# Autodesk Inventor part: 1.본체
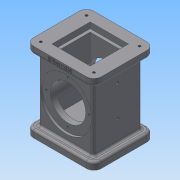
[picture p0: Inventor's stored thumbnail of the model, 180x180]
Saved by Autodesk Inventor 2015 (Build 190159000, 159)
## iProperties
Created: 2017-08
Part Number: 1.본체
Material: 일반
Document SubType Name: Modeling
Designer: owner
Density: 1 g/cm^3
Appearance: 기본값
Author: owner
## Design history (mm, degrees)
sketch "스케치1"
  geometry: L1 (-41, -46)-(41, -46); L2 (41, -46)-(41, 46); L3 (41, 46)-(-41, 46); L4 (-41, 46)-(-41, -46); L5 (-41, -46)-(41, 46); L6 (41, -46)-(-41, 46); 1 further point
  constraints: 12 end point, 2 midpoint, 2 parallel, 1 horizontal, 1 perpendicular
  dimensions: "d0" = 92 distance between parallel lines of L1 L3; "d1" = 82 distance between parallel lines of L4 L2
extrude "돌출1" new body sketch "스케치1" distance "d2" = 10; taper "d3" = 0 deg
sketch "스케치2"
  geometry: L1 (33, 37)-(-33, 37); L2 (-33, 37)-(-33, -37); L3 (-33, -37)-(33, -37); L4 (33, -37)-(33, 37); L5 (33, 37)-(-33, -37); L6 (-33, 37)-(33, -37); 1 further point
  constraints: 12 end point, 2 midpoint, 2 parallel, 1 horizontal, 1 perpendicular
  dimensions: "d4" = 74 distance between parallel lines of L1 L3; "d5" = 66 distance between parallel lines of L4 L2
extrude "돌출2" join sketch "스케치2" distance "d6" = 88; taper "d7" = 0 deg
sketch "스케치3"
  geometry: L1 (41, 46)-(-41, 46) reference; L2 (-41, 46)-(-41, -46) reference; L3 (-41, -46)-(41, -46) reference; L4 (41, -46)-(41, 46) reference; 1 further point
extrude "돌출3" join sketch "스케치3" distance "d8" = 10; taper "d9" = 0 deg
sketch "스케치5"
  geometry: L1 (26, -26)-(-26, -26); L2 (-26, -26)-(-26, 26); L3 (-26, 26)-(26, 26); L4 (26, 26)-(26, -26); L5 (26, -26)-(-26, 26); L6 (-26, -26)-(26, 26); 1 further point
  constraints: 12 end point, 2 midpoint, 2 parallel, 1 horizontal, 1 perpendicular
  dimensions: "d14" = 52 distance between parallel lines of L4 L2; "d15" = 52 distance between parallel lines of L1 L3 (= d14)
extrude "돌출5" cut sketch "스케치5" distance "d16" = 8; taper "d17" = 0 deg
sketch "스케치6"
  geometry: L1 (24, -24)-(-24, -24); L2 (-24, -24)-(-24, 24); L3 (-24, 24)-(24, 24); L4 (24, 24)-(24, -24); L5 (24, -24)-(-24, 24); L6 (-24, -24)-(24, 24); 1 further point
  constraints: 12 end point, 2 midpoint, 2 parallel, 1 horizontal, 1 perpendicular
  dimensions: "d18" = 48 distance between parallel lines of L4 L2; "d19" = 48 distance between parallel lines of L1 L3 (= d18)
extrude "돌출6" cut sketch "스케치6" distance "d20" = 16; taper "d21" = 0 deg
sketch "스케치7"
  geometry: L1 (-33, 10)-(-33, 98) reference; L2 (33, 10)-(33, 98) reference; L3 (-33, 54)-(33, 54); L4 (24, 0)-(-24, 0) reference; L5 (-33, 89)-(-30, 89); L6 (-30, 89)-(-30, 54); 1 further point
  constraints: 6 end point, 2 midpoint, 2 perpendicular, 2 point on line, 1 horizontal
  dimensions: "d22" = 54 distance between parallel lines of L4 L3; "d23" = 3 distance between parallel lines of L6 L1; "d24" = 70 diameter of L5.start L3
revolve "회전1" sketch "스케치7" stored, may be unused: angle "d25" = 90 deg
sketch "스케치8"
  geometry: C1 r 35 at (0, 0) reference; C2 r 24 at (0, 0); 1 further point
  constraints: 1 centre point, 1 coincident
  dimensions: "d26" = 48 diameter of C2
extrude "돌출7" cut sketch "스케치8" stored distance "d27" = 16; taper "d28" = 0 deg
sketch "스케치9" dims "d30" = 58
  geometry: L1 (0, 0)-(0, 29); 3 further points
  constraints: 2 coincident, 2 end point, 1 vertical, 1 vertical alignment, 2 other
hole "구멍1" sketch "스케치9" at (0, 29) diameter "d31" = 3.242; stored, may be unused: countersink angle "d35" = 90 deg, drill point angle "d37" = 118 deg; dims "d32" = 4, "d33" = 4, "d34" = 2, "d36" = 6
sketch "스케치10"
  geometry: L1 (31, -36)-(-31, -36); L2 (-31, -36)-(-31, 36); L3 (-31, 36)-(31, 36); L4 (31, 36)-(31, -36); L5 (31, -36)-(-31, 36); L6 (-31, -36)-(31, 36); 5 further points
  constraints: 12 end point, 4 coincident, 2 midpoint, 2 parallel, 1 horizontal, 1 perpendicular
  dimensions: "d41" = 62 distance between parallel lines of L4 L2; "d42" = 72 distance between parallel lines of L1 L3
hole "구멍2" sketch "스케치10" at (-31, 36), (31, 36), (31, -36), (-31, -36) diameter "d43" = 3.242; stored, may be unused: countersink angle "d47" = 90 deg, drill point angle "d49" = 118 deg; dims "d44" = 4, "d45" = 4, "d46" = 2, "d48" = 6
sketch "스케치12"
  geometry: L1 (22, -22)-(-22, -22); L2 (-22, -22)-(-22, 22); L3 (-22, 22)-(22, 22); L4 (22, 22)-(22, -22); L5 (22, -22)-(-22, 22); L6 (-22, -22)-(22, 22); 1 further point
  constraints: 12 end point, 2 midpoint, 2 parallel, 1 horizontal, 1 perpendicular
  dimensions: "d50" = 44 distance between parallel lines of L4 L2; "d51" = 44 distance between parallel lines of L1 L3
extrude "돌출8" cut sketch "스케치12" distance "d52" = 74; taper "d53" = 0 deg
fillet "모깎기1" dims "d54" = 3, "d55" = 10
sketch "스케치13"
  geometry: L1 (31, 36)-(-31, 36); L2 (-31, 36)-(-31, -36); L3 (-31, -36)-(31, -36); L4 (31, -36)-(31, 36); L5 (31, 36)-(-31, -36); L6 (-31, 36)-(31, -36); 5 further points
  constraints: 12 end point, 4 coincident, 2 midpoint, 2 parallel, 1 horizontal, 1 perpendicular
  dimensions: "d56" = 72 distance between parallel lines of L1 L3; "d57" = 62 distance between parallel lines of L4 L2
hole "구멍3" sketch "스케치13" at (-31, -36), (-31, 36), (31, 36), (31, -36) diameter "d58" = 3.242; stored, may be unused: countersink angle "d62" = 90 deg, drill point angle "d64" = 118 deg; dims "d59" = 4, "d60" = 4, "d61" = 2, "d63" = 6
sketch "스케치14"
  geometry: L1 (-0.196, 10)-(61.804, 10) reference; L2 (30.804, -98)-(30.804, 10); L3 (-0.196, -98)-(61.804, -98) reference; 2 further points
  constraints: 2 end point, 2 point on line, 1 midpoint
  dimensions: "d65" = 38 distance from line of point (30.804, -60) L3; "d66" = 42 distance of point (30.804, -60) point (30.804, -18)
hole "구멍4" sketch "스케치14" at (30.804, -60), (30.804, -18) diameter "d67" = 4.134; stored, may be unused: countersink angle "d71" = 90 deg, drill point angle "d73" = 118 deg; dims "d68" = 10, "d69" = 4, "d70" = 2, "d72" = 20.95
sketch "스케치15"
  geometry: L1 (-10, 7)-(-10, 0) reference; L2 (72, 7)-(82, 7) reference; 2 further points
  constraints: 1 other
  dimensions: "d74" = 46 distance from line of point (36, 3) L1; "d75" = 4 distance from line of L2 point (36, 3)
feature "엠보싱1" sketch "스케치15" dims "d9" = 0, "d76" = 0.5, "d77" = 0
node "솔리드1"
pattern_circular "원형 패턴1" dims angle "d39" = 360 deg
mirror "대칭1"
mirror "대칭2"
